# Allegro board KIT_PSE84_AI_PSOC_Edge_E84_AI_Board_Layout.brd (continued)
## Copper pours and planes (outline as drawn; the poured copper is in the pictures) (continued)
(no net) on TOP: outline of 273 points within 0.56,0.56 35.44,62.94 ; 176 cut-outs
(no net) on BOTTOM: outline of 111 points within 0.56,0.56 35.46,62.94 ; 219 cut-outs
DISP_VDD_3V3 on TOP: 17.93,54.92 17.98,54.87 19.68,54.87 19.79,54.97 19.79,58.37 19.74,58.42 16.92,58.42 16.71,58.22 16.71,57.38 16.87,57.23 17.75,57.23 17.93,57.05
DISP_VDD_3V3 on BOTTOM: 16.74,57.99 18.26,57.99 18.34,57.91 18.34,57.33 17.86,56.85 17.55,56.85 17.32,56.62 17.32,56.01 17.45,55.88 17.45,55.12 17.4,55.07 16.76,55.07 16.64,55.2 16.64,57.89
KP_VBUS on TOP: 28.32,6.1 28.35,6.12 28.35,7.29 28.32,7.32 28.32,8 28.42,8.1 28.91,8.1 28.96,8.15 28.96,9.98 28.91,10.03 26.44,10.03 26.24,9.83 25.71,9.83 25.5,9.83 25.43,9.75 25.43,9.37 25.48,9.32 26.19,9.32 26.39,9.53 27.94,9.53 28.09,9.37 28.09,8.89 27.97,8.76 27.48,8.76 27.36,8.89 26.65,8.89 26.49,8.74 25.73,8.74 25.73,8.74 25.5,8.74 25.45,8.69 25.45,8.36 25.53,8.28 26.26,8.28 26.52,8.03 27.51,8.03 27.74,7.8 27.74,6.12 27.76,6.1
KP_VBUS on TOP: 22.96,6.12 22.99,6.1 23.55,6.1 23.57,6.12 23.57,7.85 23.57,7.85 23.57,8.08 23.42,8.23 22.61,8.23 22.48,8.1 22.48,7.77 22.68,7.57 22.81,7.57 22.96,7.42
KP_VBUS on BOTTOM: 23.32,4.62 25.25,4.62 25.38,4.5 25.38,2.16 25.2,1.98 23.37,1.98 23.24,2.11 23.24,4.55
KP_VBUS on L03_SIG1: 25.15,8.74 28.7,8.74 28.93,8.51 28.93,4.42 26.77,2.26 23.67,2.26 22.33,3.61 22.33,8.08 22.73,8.48 23.93,8.48 23.93,7.82 24.59,7.82 24.59,8.48 24.89,8.48 ; 2 cut-outs
Net_89 on TOP (solid shape): 35.01,61.96 31.64,58.45 31.64,54.93 30.64,54.93 30.64,60.68 31.74,60.68 31.74,62.47 35.01,62.47
Net_90 on TOP (solid shape): 27.45,61.97 24.41,61.97 24.41,61.57 23.9,61.57 23.9,62.47 27.45,62.47
P5LP_VDD on L05_PWR: outline of 86 points within 16.69,8.76 30.76,27.51 ; 20 cut-outs
PE84_VBUS on TOP: 8.21,17.96 8.41,17.76 9.63,17.76 9.7,17.68 10.19,17.68 10.24,17.63 11.48,17.63 11.66,17.45 12.73,17.45 12.93,17.65 12.98,17.65 13.16,17.83 13.16,18.34 13.28,18.47 13.64,18.47 13.67,18.44 13.67,18.01 13.82,17.86 13.82,17.53 14.15,17.2 14.5,17.2 14.56,17.15 14.56,16.89 14.5,16.84 14.07,16.84 13.82,16.59 13.01,16.59 12.78,16.82 11.35,16.82 11.07,16.54 9.23,16.54 9.03,16.74 7.44,16.74 7.04,17.15 7.04,17.91 7.09,17.96
PE84_VBUS on TOP: 7.62,6.12 7.62,7.65 7.29,7.98 7.29,8.38 7.42,8.51 8.15,8.51 8.23,8.43 8.23,6.12 8.21,6.1 7.65,6.1
PE84_VBUS on TOP: 12.23,7.68 12.42,7.49 12.42,6.12 12.45,6.1 13.01,6.1 13.03,6.12 13.03,7.49 13.41,7.88 13.41,8.03 13.28,8.15 12.64,8.15 12.23,7.75
PE84_VBUS on BOTTOM: 15.27,17.96 15.83,17.96 16,18.14 16.92,18.14 17.1,17.96 17.1,17.58 18.52,16.15 18.59,16.08 18.59,15.6 18.49,15.5 18.01,15.5 17.88,15.62 17.88,15.83 17.58,16.13 17.3,16.13 16.03,17.4 15.32,17.4 15.24,17.48 15.24,17.93
PE84_VBUS on BOTTOM: 8.28,17.83 8.28,17.22 8,16.94 8,16.94 8,13.03 8.13,12.91 8.13,8.41 8.33,8.21 8.33,7.37 8.61,7.09 8.61,3.84 8.71,3.73 8.89,3.73 9.6,3.02 9.91,3.02 10.08,2.85 10.08,2.69 10.09,2.69 10.09,0.89 9.93,0.74 8.33,0.74 8.23,0.84 8.23,1.63 7.72,2.13 7.72,5.21 7.8,5.28 7.8,6.66 7.46,7 7.46,7.28 6.81,7.93 6.81,10.49 6.03,11.27 6.03,15.66 5.82,15.88 5.82,17.81 5.99,17.98 8.13,17.98
PE84_VBUS on L03_SIG1: 8.08,8.61 8.43,8.26 8.43,7.57 8.61,7.39 11.81,7.39 12.12,7.7 12.22,7.7 12.52,8 12.62,8 12.8,8.18 13.36,8.18 13.54,8 13.54,7.85 13.84,7.54 14.25,7.54 14.43,7.37 14.43,2.74 13.9,2.21 7.57,2.21 7.16,2.62 7.16,8.46 7.32,8.61 ; 3 cut-outs
PE84_VBUS on L04_SIG2: 18.72,16.13 18.95,15.9 18.95,13.92 18.34,13.31 18.34,11.08 18.52,10.9 18.52,9.96 18.34,9.78 16.76,9.78 16.05,10.49 16.05,14.68 16.26,14.89 16.26,16 16.38,16.13
PE84_VBUS on L05_PWR: 15.19,8.38 15.52,8.05 17.58,8.05 17.83,8.31 17.83,10.47 17.98,10.62 19.03,10.62 19.2,10.44 19.2,5.64 18.18,4.61 13.14,4.61 12.85,4.9 12.85,8.18 13.06,8.38
PE84_VTARG on TOP: 14.3,48.67 18.54,48.67 18.59,48.62 18.59,47.73 18.49,47.63 16.28,47.63 15.93,47.27 15.93,46.69 15.16,46.69 15.16,45.8 14.27,45.8 14.22,45.85 14.22,48.59
PE84_VTARG on L05_PWR: 17.22,45.77 24.64,45.77 26.01,44.4 26.01,41.05 25.7,41.05 25.7,40.59 26.01,40.59 27.58,39.02 27.58,37.14 27.46,37.14 26.54,36.22 26.34,36.22 26.16,36.4 26.16,37.36 25.96,37.57 21.29,37.57 20.14,36.42 20.14,34.32 19.41,33.58 17.91,33.58 17.91,33.91 17.25,34.57 15.9,34.57 15.27,35.21 15.27,35.92 13.74,37.44 13.74,40.79 13,41.53 12.78,41.53 12.14,42.16 12.14,44.73 12.88,45.47 12.88,45.11 13.46,45.11 13.46,45.7 13.11,45.7 13.18,45.77 15.27,45.77 15.37,45.87 17.12,45.87 ; 3 cut-outs
N17713209 on BOTTOM: 12.55,10.16 12.5,10.21 12.5,11.28 12.78,11.56 12.78,15.98 12.83,16.03 14.07,16.03 14.3,15.8 14.3,15.19 14.3,15.19 14.3,11.99 14.2,11.89 13.74,11.89 13.16,11.3 13.01,11.3 12.88,11.18 12.88,10.52 12.98,10.42 14.23,10.42 14.25,10.39 14.25,10.21 14.2,10.16
N17865809 on BOTTOM: 13.64,26.09 13.72,26.01 14.28,26.01 14.33,26.06 14.33,27.43 14.45,27.56 15.06,27.56 15.17,27.66 15.17,27.86 15.22,27.92 15.22,30.05 15.17,30.1 13.69,30.1 13.64,30.05
N17879800 on BOTTOM: 10.64,20.42 10.69,20.37 10.69,19.89 8.46,19.89 8.36,19.99 8.36,20.91 8.46,21.01 8.87,21.01 8.89,20.98 8.89,20.58 9.04,20.42

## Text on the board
BOTTOM: BOTTOM
Ref Des/Assembly Bottom: ASSEMBLY DRAWING BOTTOM
Package Geometry/Pastemask Bottom: PASTE MASK BOTTOM
Ref Des/Silkscreen Bottom: A | 24 | R51 | C16 | R47 | R45 | C115 | R49 | C121 | C31 | R21 | R66 | R22 | FB4 | R24 | R15 | R16 | C27 | R29 | R28 | FB9 | C119 | C17 | C116 | C35 | R23 | R91 | MIC | ANG | SPEAKER | REV 3.0 | 600-60751-01 | SILKSCREEN BOTTOM
User.Comments: SOLDER MASK TOP | SOLDER MASK BOTTOM
TOP: TOP
Ref Des/Assembly Top: R209 | R156 | ASSEMBLY DRAWING TOP
Package Geometry/Pastemask Top: PASTE MASK TOP
Ref Des/Silkscreen Top: BATTERY | INPUT | TM | C66 | ALG | DIG | R159 | R73 | R87 | PSE84-USB | ( | R88 | R9 | C1 | USER | C58 | RST | R63 | R54 | R52 | R62 | R65 | R50 | R48 | R8 | C67 | FB10 | R46 | R58 | C81 | R31 | PSOC  EDGE E84 | KP3-USB | C4 | RADAR | 1 | -DSI | MIPI | C57 | FB3 | C93 | C84 | R85 | R210 | R213 | C71 | AI KIT | SILKSCREEN TOP
L02_GND: L02_GND1
L03_SIG1: L03_SIG1
L04_SIG2: L04_SIG2
L05_PWR: LO5_GND2
DIMENSION: TOTOAL 4 no's on Top layer | SHORT NET GND AND AGND | DETAIL3_TOP | 2.00X4
User.7: TM
User.8: 1. SPECIFICATIONS/TOLERANCES: | 2 | 3. DRILLING: | 4. SOLDER MASK: | 5. MARKING: | 6. ELECTRICAL TEST: | 7 | 8. IMPEDANCE: | 9. IF PANELIZATION SPECIFICATIONS ARE PROVIDED, THE PCBS SHALL BE DELIVERED IN | A. FABRICATE PER IPC-6012, CLASS 2, USING PROVIDED DATA FILES | B. ALL SPECIFICATIONS USED SHALL BE PER THEIR LATEST REVISIONS. | C. THE DIMENSIONS OF CIRCUIT FEATURES IN THE PROVIDED DATA MAY BE ADJUSTED | D. REMOVE ALL BURRS AND BREAK SHARP EDGES, .381 [.015] MAX RADIUS. | E. PARENTHETICAL INFORMATION IS FOR REFERENCE ONLY. | F. REPAIR OF PCB DEFECTS IS NOT PERMITTED. | DIELECTRIC MATERIAL: | A. DIELECTRIC MATERIAL SHALL BE PER IPC-4101/99, /124, /126 OR /129 | B. MINIMUM DIELECTRIC THICKNESS SHALL BE .051 [.002] FOR REFERENCED STACK-UP | C. SEE LAYER STACK-UP FOR REQUIRED COPPER WEIGHTS AND THE FINISHED PCB | D. FINISHED PCB THICKNESS SHALL BE MEASURED OVER LANDS AND/OR | A. VIA DIAMETERS (TOL. = +.051/- DRILL DIAMETER [+.0020/- DRILL DIAMETER]) | B. LAYER-TO-LAYER MISREGISTRATION SHALL BE .127 [.005] MAXIMUM. | A. APPLY LPI SOLDER MASK USING PROVIDED DATA. | B. SOLDER MASK SHALL BE PER IPC-SM-840, CLASS T, COLOR BLACK | C. THE DIMENSIONS OF SOLDER MASK-DEFINED PADS ON PLANES AND/OR WIDE | A. MARK PCB PER PROVIDED DATA USING SILKSCREEN OR AUTOMATED INJET | B. SUPPLIER ID AND TRACEABILITY INFORMATION SHALL BE APPLIED USING | C. INK SHALL NOT BE APPLIED TO ANY SOLDERABLE SURFACE. | A. DESIGN VERIFICATION SHALL BE DONE PRIOR TO PCB FABRICATION USING | B. ALL PCBS SHALL BE 100% ELECTRICALLY TESTED FOR OPENS AND SHORTS | C. APPLY TEST STAMP IN NON-LEGEND AREA ON REAR SIDE OF PCB; OK TO APPLY | FINAL FINISH: | A. FINAL FINISH SHALL BE ELECTROLESS NICKEL/IMMERSION GOLD (ENIG) PER IPC-4552. | A. IMPEDANCE TOLERANCE SHALL BE +/- 10%. | B. SEE LAYER STACK-UP FOR IMPEDANCE REQUIREMENTS. | PANEL FORM. HOWEVER, THESE SPECIFICATIONS MAY BE CHANGED AS REQUIRED BY THE | CONTRACT MANUFACTURER TO SUPPORT VOLUME ASSEMBLY REQUIREMENTS. | NOTE: DONT ADD MOUSE BITE IN AND AROUND J1 AND J2 USB HEADER,ADD IT IN BOARD EDGE | 3C.FOLLOW TYPE-7 VIA FILLING THROUGH OUT BOARD, FILL ALL THRU VIAS USING CONDUCTIVE  AND OVERPLATE WITH COPPER, .005 [.0002] | 600-60751-01_03.TGZ OR 600-60751-01_03.ZIP. | ONLY TO COMPENSATE FOR PROCESS TOLERANCES; ADDING, REMOVING OR RELOCATING | CIRCUIT FEATURES, INCLUDING NON-FUNCTIONAL PADS, IS NOT ALLOWED, AND THE | DESIGN OF ALL PLANE STRUCTURES MUST BE MAINTAINED TO ENSURE PROPER | ELECTRICAL PERFORMANCE. | (RoHS COMPLIANT EPOXY-GLASS,USE TU-872 SLK MATERIAL OR EQUIVALENT) | DIMENSIONS OF.076 [.003] OR GREATER; IPC-6012 REQUIREMENTS SHALL OTHERWISE | APPLY. SINGLE-PLY CONSTRUCTION IS ALLOWED. | THICKNESS. IF SPECIFIED, 1/3 OZ. STARTING FOIL MAY BE ACHIEVED BY 1/2 OZ. | FOIL REDUCTION. | CONDUCTORS NOT COVERED BY SOLDER MASK. | SHALL BE VERIFIED BEFORE PLATING; ALL OTHER HOLE DIAMETERS SHALL BE | VERIFIED AT FINAL INSPECTION. | CONDUCTORS SHALL NOT BE MODIFIED. | PROCESSING WITH PERMANENT, NON-CONDUCTIVE INK, COLOR WHITE. | PERMANENT, NON-CONDUCTIVE INK, COLOR WHITE.IN THE UNUSED REAR SIDE | SUPPLIED VALOR ODB++ DATABASE, OR GERBER DATA AND AN IPC-D-356 NETLIST. | USING PROVIDED DATA. | TO PANEL RAILS IF SPACE DOES NOT PERMIT. | MINIMUM THICKNESS. DIMPLE DEPTH IN BGA PADS SHALL BE .025 [.001] MAXIMUM. THE PRESENCE | OF WRAP PLATING SHALL BE VISUALLY EVIDENT IN ALL QUALITY CONFORMANCE MICROSECTIONS; NO | MINIMUM MEASUREMENT REQUIRED. | NOTES: UNLESS OTHERWISE SPECIFIED | THRU-VIA CONDUCTIVE FILLING NOTE (VIA-IN-PAD CONSTRUCTION)
User.9: L05 - GND2 | L06 - BOTTOM | 1.26 | 1.85 | -- | 50E | --- | 5.9 | 05 | ----- | 02 | 90E | ---/--- | 4.5/5.3 | 4.5/4.5 | DIFF | IMP | OHMS | 100E | ---- | WIDTH/SPACE | 4.0/6.0 | 4.0/7.1 | TRACE | (3.558) | (5.00) | REF | LAYER
User.11: 2
User.12: TM
User.13: DIMENSIONS IN MM [INCH]
User.22: PROJECT: | DRAWN BY: | LAYER: | DWG NO: | REV: | DATE: | TM | Am Campeon 1-15 | Infineon Technologies AG | 85579 NEUBIBERG - GERMANY | PSOC  EDGE E84 AI BOARD | 620-60751-01 | PRAO | 03 | 05/19/25
User.23: FIGURE | FINISHED_SIZE | 7.87 | 8.0 | 10.0 | 39.37 | 41.34 | 70.08 | 25.59 | 31.5 | 118.11 | 55.12x23.62 | 66.93x23.62 | DRILLED_SIZE | - | DRILL CHART: TOP to BOTTOM | ALL UNITS ARE IN MILS | FINISHED_TOL | +3.0/-3.0 | +2.0/-2.0 | DRILLED_TOL | PLATED | NON-PLATED | QTY | 5 | 430 | 318 | 6 | 20 | 1 | 4 | 800 | TOTAL HOLES:
User.27: TOTAL 1no's SHORT NET ON BOARD | SHORT NET GND AND AGND
User.42: DETAIL3_BOTTOM
